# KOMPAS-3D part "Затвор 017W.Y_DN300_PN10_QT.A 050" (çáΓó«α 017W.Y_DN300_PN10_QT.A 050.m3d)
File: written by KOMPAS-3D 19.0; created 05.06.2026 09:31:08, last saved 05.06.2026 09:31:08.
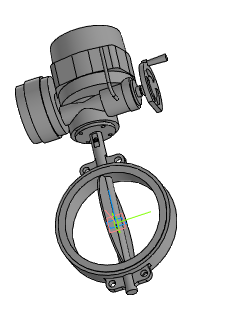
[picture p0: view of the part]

Document properties: Автор: Энергия; Полное имя файла: ..\..\..\3d для проектировщиков\x.x Тип 017W.Y(S) Затвор дисковый поворотный межфланцевый\Затвор 017W.Y(S)_DN32-DN1200_QT.A_MT903.A\Затвор 017W.Y_DN300_PN10_QT.A 050.a3d

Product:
- Part/product: Затвор 017W.Y_DN300_PN10_QT.A 050
    Масса: 140.411

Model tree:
1. Операция без истории:1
